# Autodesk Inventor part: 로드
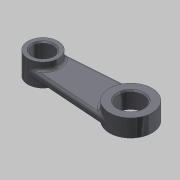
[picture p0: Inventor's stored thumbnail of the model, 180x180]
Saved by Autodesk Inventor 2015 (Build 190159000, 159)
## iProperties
Created: 2015-10
Part Number: 로드
Document SubType Name: Modeling
Designer: mdu
Density: 7.86 g/cm^3
Material: 강철, 연강
Mass: 20.3759 g
Surface Area: 22.2266 cm^2
Volume: 2.59236 cm^3
Appearance: 강철 - 광택
Author: mdu
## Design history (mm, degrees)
sketch "스케치1"
  geometry: L1 (13.821, 5.985)-(48.643, 8.478); L2 (48.643, -8.478)-(13.821, -5.985); C1 r 4 at (14.25, 0) reference; A1 r 6 centre (14.25, 0) between (13.821, 5.985) and (13.821, -5.985); A2 r 8.5 centre (49.25, 0) between (48.643, 8.478) and (48.643, -8.478); 1 further point
  constraints: 4 end point, 4 point on circle, 4 tangent, 2 centre point, 1 coincident, 1 horizontal alignment
  dimensions: "d0" = 12 diameter of A1; "d1" = 35 distance of A2.centre A1.centre; "d2" = 17 diameter of A2
  node "참조1"
extrude "돌출1" new body sketch "스케치1" distance "d3" = 9; taper "d4" = 0 deg
node "작업 평면1"
node "작업 평면2"
extrude "돌출2" join sketch "스케치1" stored distance "d7" = 10; taper "d8" = 0 deg
node "작업 평면3"
extrude "돌출3" join sketch "스케치1" stored distance "d10" = 10; taper "d11" = 0 deg
hole "구멍1" diameter "d14" = 10; stored, may be unused: countersink angle "d18" = 90 deg, drill point angle "d20" = 118 deg; dims "d12" = 10, "d13" = 10, "d15" = 6, "d16" = 4, "d17" = 2, "d19" = 8
fillet "모깎기1" dims "d21" = 1
chamfer "모따기1" distance "d22" = 0.5; stored, may be unused: second distance "d23" = 2, angle "d24" = 45 deg
chamfer "모따기2" distance "d25" = 0.5; stored, may be unused: second distance "d26" = 2, angle "d27" = 45 deg
node "솔리드1"
other parameters: "d5" = -6, "d6" = -3, "d9" = -4
